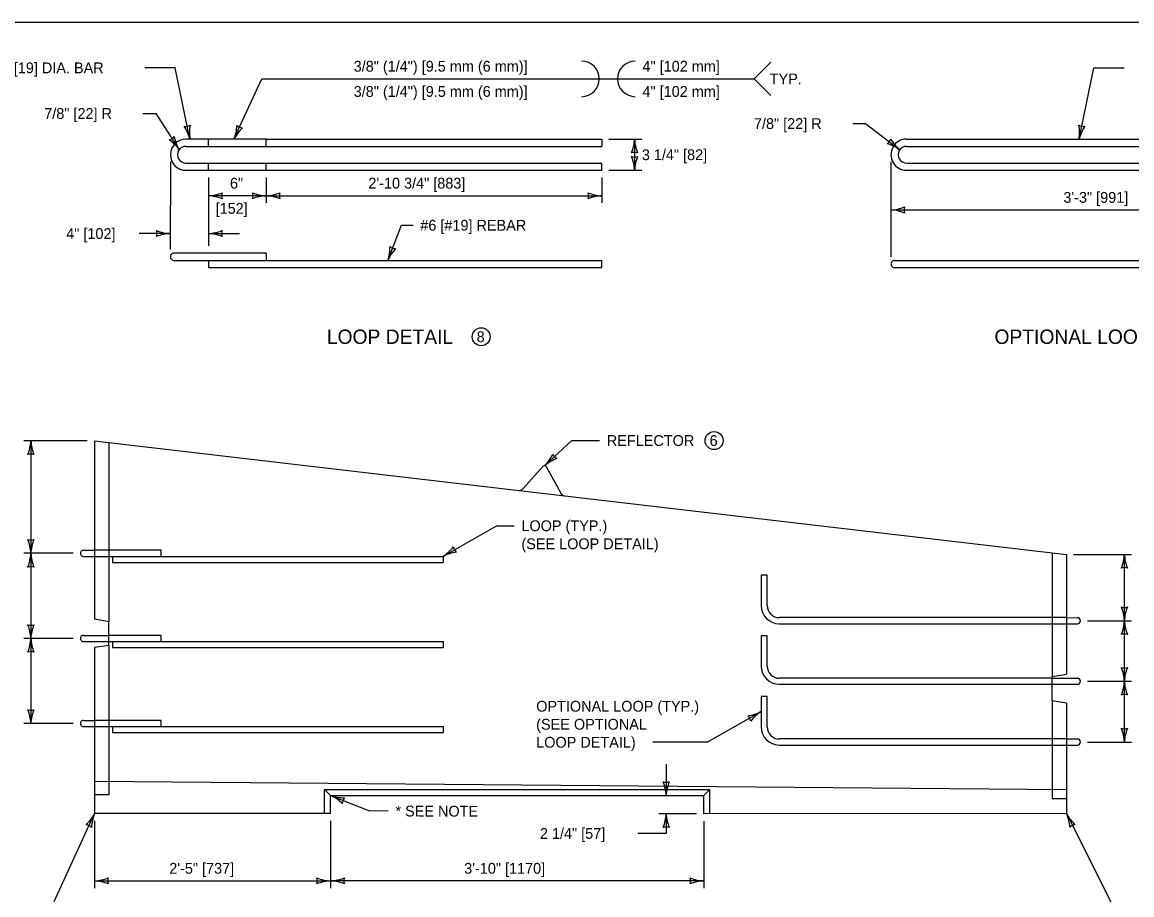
# Model space of a CAD drawing. Extents: x 49991.4 to 50021, y 49987.6 to 50011.4.
# Drawn here: x 50003.46 to 50009.63, y 49994.15 to 49999 of the extents above; entities that cross this region are included whole.
import ezdxf

# ---------------------------------------------------------------- set-up
doc = ezdxf.new("R2010")
doc.units = 0
for name, color, linetype in [('Level 1', 7, 'Continuous'), ('Level 2', 7, 'Continuous'), ('Level 3', 7, 'Continuous'), ('Level 4', 7, 'Continuous')]:
    doc.layers.add(name, color=color, linetype=linetype)

msp = doc.modelspace()

# ---------------------------------------------------------------- linework, layer by layer
at = {"layer": 'Level 1'}
for p, q in [((50004.8177, 49998.3499), (50004.3721, 49998.3499)), ((50004.8177, 49998.3499), (50006.6825, 49998.3499)), ((50004.8177, 49998.3098), (50004.8177, 49998.3499)), ((50006.6825, 49998.3499), (50006.6825, 49998.3098)), ((50008.376, 49998.3499), (50010.6665, 49998.3499)), ((50004.3718, 49998.3098), (50006.6825, 49998.3098)), ((50008.376, 49998.3098), (50010.6665, 49998.3098)), ((50004.3718, 49998.2169), (50006.6825, 49998.2169)), ((50004.8177, 49998.1767), (50004.8177, 49998.2169)), ((50006.6825, 49998.1767), (50006.6825, 49998.2169)), ((50008.3757, 49998.2169), (50010.6665, 49998.2169)), ((50004.3721, 49998.1767), (50004.8177, 49998.1767)), ((50004.8177, 49998.1767), (50006.6825, 49998.1767)), ((50006.6825, 49998.1767), (50006.6825, 49998.1767)), ((50008.376, 49998.1767), (50008.8216, 49998.1767)), ((50008.5005, 49998.1767), (50010.6665, 49998.1767)), ((50004.8177, 49997.7169), (50004.3055, 49997.7169)), ((50004.3055, 49997.6768), (50006.6825, 49997.6768)), ((50004.4966, 49997.6768), (50004.4966, 49997.6367)), ((50004.8177, 49997.7169), (50004.8177, 49997.6768)), ((50006.6825, 49997.6367), (50006.6825, 49997.6768)), ((50008.3092, 49997.6768), (50010.5663, 49997.6768)), ((50004.4966, 49997.6367), (50006.6825, 49997.6367)), ((50008.3092, 49997.6367), (50010.5663, 49997.6367)), ((50003.8641, 49996.6742), (50009.2642, 49996.0442)), ((50003.8641, 49996.6742), (50003.8641, 49995.6844)), ((50003.8022, 49996.0668), (50003.8641, 49996.0666)), ((50003.8022, 49996.033), (50003.8641, 49996.0329)), ((50009.2642, 49996.0442), (50009.2642, 49995.3789)), ((50009.2642, 49995.6926), (50009.3248, 49995.6925)), ((50003.9431, 49995.6691), (50003.8641, 49995.6844)), ((50003.9431, 49995.5388), (50003.9431, 49995.6691)), ((50009.2642, 49995.6589), (50009.3248, 49995.659)), ((50003.8023, 49995.5942), (50003.9431, 49995.5943)), ((50003.8023, 49995.5605), (50003.9431, 49995.5606)), ((50003.9431, 49995.5388), (50003.8642, 49995.5269)), ((50003.8642, 49995.5269), (50003.8642, 49994.6042)), ((50009.1855, 49995.3665), (50009.2642, 49995.3789)), ((50009.1855, 49995.2326), (50009.1855, 49995.3665)), ((50009.1855, 49995.3561), (50009.3248, 49995.3559)), ((50009.1855, 49995.3224), (50009.3248, 49995.3224)), ((50009.1855, 49995.2326), (50009.2642, 49995.2202)), ((50009.2642, 49995.2202), (50009.2642, 49994.6042)), ((50003.8023, 49995.1217), (50003.8642, 49995.122)), ((50003.8023, 49995.088), (50003.8642, 49995.0884)), ((50009.2642, 49995.0189), (50009.3248, 49995.0189)), ((50009.2642, 49994.9852), (50009.3248, 49994.9852)), ((50005.1425, 49994.6042), (50005.1425, 49994.7388)), ((50005.1425, 49994.7388), (50005.1761, 49994.705)), ((50005.1425, 49994.7388), (50007.2826, 49994.7388)), ((50005.1761, 49994.705), (50007.249, 49994.705)), ((50005.1761, 49994.6042), (50005.1761, 49994.705)), ((50007.2826, 49994.7388), (50007.249, 49994.705)), ((50007.249, 49994.6033), (50007.249, 49994.705)), ((50007.2826, 49994.6033), (50007.2826, 49994.7388)), ((50005.1761, 49994.6042), (50003.8642, 49994.6042)), ((50009.2642, 49994.6042), (50007.249, 49994.6033))]:
    msp.add_line(p, q, dxfattribs=at)
msp.add_lwpolyline([(49999.3835, 49998.9992), (50016.7501, 49998.9992), (50016.7501, 49987.7988), (49999.3835, 49987.7988)], close=True, dxfattribs=at)
for centre, radius, start, end in [((50004.3721, 49998.2633), 0.0866, 90, 270), ((50008.3758, 49998.2633), 0.0866, 89.85968, 270.14031), ((50004.3718, 49998.2633), 0.0465, 89.99697, 270.00303), ((50008.3755, 49998.2634), 0.0465, 89.36692, 270.33621), ((50004.3055, 49997.6969), 0.0201, 90.02933, 269.97067), ((50008.3092, 49997.6568), 0.02, 89.86684, 270.13311), ((50003.8022, 49996.0499), 0.0169, 89.95241, 270.04759), ((50009.3247, 49995.6758), 0.0168, 270.36731, 89.67733), ((50009.3248, 49995.3392), 0.0168, 270.24332, 90.00199), ((50003.8023, 49995.1049), 0.0169, 89.95713, 270.04287), ((50009.3248, 49995.002), 0.0169, 270.1612, 89.88321)]:
    msp.add_arc(centre, radius, start, end, dxfattribs=at)
msp.add_ellipse((50003.8023, 49995.5773), major_axis=(0, 0.0169), ratio=0.999599, start_param=0, end_param=3.141593, dxfattribs=at)
at = {"layer": 'Level 2'}
for centre in [(50006.0124, 49997.2526), (50007.3063, 49996.6761)]:
    msp.add_circle(centre, 0.05, dxfattribs=at)
at = {"layer": 'Level 3'}
for p, q in [((50007.5293, 49998.6845), (50007.6227, 49998.7779)), ((50007.5293, 49998.6845), (50007.6227, 49998.5913)), ((50004.1332, 49998.4923), (50004.2045, 49998.4923)), ((50004.2044, 49998.4922), (50004.3346, 49998.2911)), ((50008.0765, 49998.4362), (50008.1478, 49998.4362)), ((50008.1478, 49998.4362), (50008.3383, 49998.2912)), ((50006.7225, 49998.3499), (50006.905, 49998.3499)), ((50006.865, 49998.3499), (50006.865, 49998.1767)), ((50004.2855, 49998.2233), (50004.2853, 49997.7369)), ((50008.2892, 49998.2233), (50008.2892, 49997.6968)), ((50006.7225, 49998.1767), (50006.905, 49998.1767)), ((50004.4966, 49998.1367), (50004.4966, 49997.7569)), ((50004.8176, 49998.1367), (50004.8176, 49997.9953)), ((50006.6824, 49998.1367), (50006.6824, 49997.9953)), ((50004.8176, 49998.0353), (50004.4966, 49998.0353)), ((50004.8176, 49998.0353), (50006.6824, 49998.0353)), ((50010.6865, 49997.9563), (50008.2892, 49997.9563)), ((50004.2853, 49997.8254), (50004.1118, 49997.8254)), ((50004.4966, 49997.8254), (50004.6701, 49997.8254)), ((50003.8241, 49996.6742), (50003.4705, 49996.6742)), ((50003.5105, 49996.6742), (50003.5105, 49996.0498)), ((50006.3662, 49996.5368), (50006.5162, 49996.6761)), ((50006.5162, 49996.6761), (50006.6707, 49996.6761)), ((50006.3576, 49996.5335), (50006.2451, 49996.4091)), ((50006.3738, 49996.5316), (50006.4541, 49996.3843)), ((50006.0997, 49996.2029), (50005.8005, 49996.0329)), ((50006.0997, 49996.2029), (50006.1961, 49996.2029)), ((50003.7453, 49996.0498), (50003.4705, 49996.0498)), ((50003.5105, 49996.0498), (50003.5105, 49995.5773)), ((50009.3042, 49996.0442), (50009.6262, 49996.0442)), ((50009.5862, 49995.6758), (50009.5862, 49996.0442)), ((50009.3815, 49995.6758), (50009.6262, 49995.6758)), ((50009.5862, 49995.3392), (50009.5862, 49995.6758)), ((50003.7454, 49995.5773), (50003.4705, 49995.5773)), ((50003.5105, 49995.5773), (50003.5105, 49995.1048)), ((50009.3816, 49995.3392), (50009.6262, 49995.3392)), ((50009.5862, 49995.002), (50009.5862, 49995.3392)), ((50007.2686, 49995.0006), (50007.5678, 49995.1706)), ((50003.7454, 49995.1048), (50003.4705, 49995.1048)), ((50007.2686, 49995.0006), (50006.9657, 49995.0006)), ((50009.3817, 49995.002), (50009.6262, 49995.002)), ((50007.0404, 49994.8784), (50007.0404, 49994.705)), ((50005.1761, 49994.705), (50005.3919, 49994.6191)), ((50003.6395, 49994.1166), (50003.8642, 49994.6042)), ((50005.4962, 49994.6188), (50005.3919, 49994.6191)), ((50007.209, 49994.6033), (50007.0004, 49994.6033)), ((50007.0404, 49994.6033), (50007.0404, 49994.4942)), ((50009.2642, 49994.6042), (50009.548, 49994.0405)), ((50003.8642, 49994.5642), (50003.8642, 49994.1907)), ((50005.1761, 49994.5642), (50005.1761, 49994.1907)), ((50007.249, 49994.5633), (50007.249, 49994.1907)), ((50007.0404, 49994.4942), (50006.8832, 49994.4942)), ((50003.8642, 49994.2307), (50005.1761, 49994.2307)), ((50007.249, 49994.2307), (50005.1761, 49994.2307))]:
    msp.add_line(p, q, dxfattribs=at)
for points in [[(50004.3941, 49998.3499), (50004.3121, 49998.7457), (50004.1429, 49998.7457)], [(50009.3344, 49998.3499), (50009.4164, 49998.7457), (50009.5856, 49998.7457)], [(50004.639, 49998.3499), (50004.7931, 49998.6848), (50007.5293, 49998.6845)], [(50005.4941, 49997.6768), (50005.5693, 49997.8715), (50005.6343, 49997.8715)]]:
    msp.add_lwpolyline(points, dxfattribs=at)
for centre, radius, start, end in [((50006.5699, 49998.6845), 0.0989, 270, 90), ((50006.8687, 49998.6845), 0.0989, 90, 270), ((50004.3681, 49998.4754), 0.0548, 263.84977, 299.57213), ((50004.1686, 49998.2914), 0.233, 14.53826, 33.78811), ((50004.6135, 49998.386), 0.2223, 169.16696, 189.35047), ((50004.4228, 49998.4367), 0.233, 338.11863, 357.36848), ((50004.837, 49998.2487), 0.2223, 132.74733, 152.93084), ((50004.6926, 49998.4664), 0.0548, 227.43014, 263.1525), ((50009.115, 49998.386), 0.2223, 350.64953, 10.83304), ((50009.3604, 49998.4755), 0.0548, 240.42787, 276.15023), ((50009.5599, 49998.2914), 0.233, 146.21189, 165.46174), ((50004.2649, 49998.3988), 0.0548, 285.05282, 320.77518), ((50004.1454, 49998.155), 0.233, 35.74131, 54.99116), ((50004.526, 49998.4041), 0.2223, 190.37001, 210.55352), ((50006.6429, 49998.3591), 0.2223, 337.45601, 357.63952), ((50007.0978, 49998.3614), 0.233, 182.82731, 202.07716), ((50008.2362, 49998.3689), 0.0548, 304.85047, 340.57283), ((50008.4801, 49998.4624), 0.2223, 210.16766, 230.35117), ((50006.865, 49998.2217), 0.0548, 72.13882, 107.86118), ((50008.2064, 49998.0991), 0.233, 55.53896, 74.78881), ((50006.865, 49998.3049), 0.0548, 252.13882, 287.86118), ((50006.6323, 49998.1652), 0.233, 2.82731, 22.07716), ((50007.0872, 49998.1675), 0.2223, 157.45601, 177.63952), ((50004.4851, 49998.268), 0.233, 272.82731, 292.07716), ((50004.4875, 49997.8132), 0.2223, 67.45601, 87.63952), ((50004.6248, 49998.0353), 0.0548, 162.13882, 197.86118), ((50004.8267, 49998.2574), 0.2223, 247.45601, 267.63952), ((50004.6893, 49998.0353), 0.0548, 342.13882, 17.86118), ((50004.8291, 49997.8026), 0.233, 92.82731, 112.07716), ((50004.8061, 49998.268), 0.233, 272.82731, 292.07716), ((50004.8084, 49997.8132), 0.2223, 67.45601, 87.63952), ((50004.9458, 49998.0353), 0.0548, 162.13882, 197.86118), ((50006.6916, 49998.2574), 0.2223, 247.45601, 267.63952), ((50006.5542, 49998.0353), 0.0548, 342.13882, 17.86118), ((50006.6939, 49997.8026), 0.233, 92.82731, 112.07716), ((50008.2777, 49998.189), 0.233, 272.82731, 292.07716), ((50008.4174, 49997.9563), 0.0548, 162.13882, 197.86118), ((50008.28, 49997.7341), 0.2223, 67.45601, 87.63952), ((50004.2945, 49998.0475), 0.2223, 247.45601, 267.63952), ((50004.1571, 49997.8254), 0.0548, 342.13882, 17.86118), ((50004.2968, 49997.5927), 0.233, 92.82731, 112.07716), ((50004.4851, 49998.0581), 0.233, 272.82731, 292.07716), ((50004.4875, 49997.6033), 0.2223, 67.45601, 87.63952), ((50004.6249, 49997.8254), 0.0548, 162.13882, 197.86118), ((50005.2729, 49997.7498), 0.233, 341.72472, 0.97457), ((50005.6981, 49997.5883), 0.2223, 136.35342, 156.53693), ((50005.5403, 49997.7964), 0.0548, 231.03623, 266.75859), ((50003.2883, 49996.6833), 0.2223, 337.45803, 357.64153), ((50003.7432, 49996.6857), 0.233, 182.82933, 202.07918), ((50003.5105, 49996.546), 0.0548, 72.14083, 107.86319), ((50006.1994, 49996.6995), 0.233, 315.70582, 334.95567), ((50006.5106, 49996.3678), 0.2223, 110.33452, 130.51802), ((50006.4601, 49996.624), 0.0548, 205.01732, 240.73968), ((50006.365, 49996.5268), 0.01, 28.58922, 137.89134), ((50006.2229, 49996.4292), 0.03, 263.24028, 317.89134), ((50006.4804, 49996.3987), 0.03, 208.58922, 253.11239), ((50003.5105, 49996.178), 0.0548, 252.14083, 287.86319), ((50003.2778, 49996.0383), 0.233, 2.82932, 22.07917), ((50003.7326, 49996.0407), 0.2223, 157.45802, 177.64153), ((50005.6828, 49996.2215), 0.2223, 301.96607, 322.14958), ((50005.912, 49996.0962), 0.0548, 191.74441, 227.46677), ((50003.2883, 49996.059), 0.2223, 337.45803, 357.64153), ((50003.7432, 49996.0613), 0.233, 182.82933, 202.07918), ((50005.9055, 49995.8248), 0.233, 97.52843, 116.77828), ((50009.3641, 49996.0533), 0.2223, 337.45601, 357.63952), ((50009.8189, 49996.0557), 0.233, 182.82731, 202.07716), ((50003.5105, 49995.9216), 0.0548, 72.14083, 107.86319), ((50009.5862, 49995.916), 0.0548, 72.13882, 107.86118), ((50009.5862, 49995.804), 0.0548, 252.13882, 287.86118), ((50009.3535, 49995.6643), 0.233, 2.82731, 22.07716), ((50009.8084, 49995.6666), 0.2223, 157.45601, 177.63952), ((50003.5105, 49995.7055), 0.0548, 252.14083, 287.86319), ((50003.2778, 49995.5658), 0.233, 2.82932, 22.07917), ((50003.7326, 49995.5682), 0.2223, 157.45802, 177.64153), ((50009.3641, 49995.6849), 0.2223, 337.45601, 357.63952), ((50009.8189, 49995.6873), 0.233, 182.82731, 202.07716), ((50003.2884, 49995.5865), 0.2223, 337.45803, 357.64153), ((50003.7432, 49995.5888), 0.233, 182.82933, 202.07918), ((50009.5862, 49995.5476), 0.0548, 72.13882, 107.86118), ((50003.5105, 49995.4491), 0.0548, 72.14083, 107.86319), ((50009.5862, 49995.4674), 0.0548, 252.13882, 287.86118), ((50009.3535, 49995.3277), 0.233, 2.82731, 22.07716), ((50009.8084, 49995.33), 0.2223, 157.45601, 177.63952), ((50009.3641, 49995.3483), 0.2223, 337.45601, 357.63952), ((50009.8189, 49995.3507), 0.233, 182.82731, 202.07716), ((50009.5862, 49995.211), 0.0548, 72.13882, 107.86118), ((50003.5105, 49995.233), 0.0548, 252.14083, 287.86319), ((50003.2778, 49995.0933), 0.233, 2.82932, 22.07917), ((50003.7326, 49995.0957), 0.2223, 157.45802, 177.64153), ((50007.4628, 49995.3786), 0.233, 277.52842, 296.77828), ((50007.4563, 49995.1073), 0.0548, 11.74441, 47.46677), ((50007.6855, 49994.982), 0.2223, 121.96607, 142.14957), ((50009.5862, 49995.1302), 0.0548, 252.13882, 287.86118), ((50009.3535, 49994.9905), 0.233, 2.82731, 22.07716), ((50009.8084, 49994.9928), 0.2223, 157.45601, 177.63952), ((50007.0404, 49994.8332), 0.0548, 252.13882, 287.86118), ((50006.8077, 49994.6935), 0.233, 2.82731, 22.07716), ((50007.2625, 49994.6958), 0.2223, 157.45601, 177.63952), ((50005.2497, 49994.9148), 0.2223, 250.65985, 270.84336), ((50005.0794, 49994.493), 0.233, 46.22221, 65.47206), ((50005.2952, 49994.6576), 0.0548, 140.43819, 176.16055), ((50003.6663, 49994.7055), 0.2223, 312.71539, 332.89889), ((50004.0803, 49994.5172), 0.233, 158.08669, 177.33654), ((50006.8183, 49994.6124), 0.2223, 337.45601, 357.63952), ((50007.2731, 49994.6148), 0.233, 182.82731, 202.07716), ((50009.0617, 49994.5125), 0.2223, 4.18325, 24.36676), ((50009.4669, 49994.7191), 0.233, 209.55455, 228.8044), ((50003.8105, 49994.4877), 0.0548, 47.39819, 83.12056), ((50007.0404, 49994.4751), 0.0548, 72.13882, 107.86118), ((50009.3219, 49994.4897), 0.0548, 98.86606, 134.58842), ((50003.8527, 49994.4634), 0.233, 272.82731, 292.07716), ((50003.855, 49994.0086), 0.2223, 67.45601, 87.63952), ((50003.9924, 49994.2307), 0.0548, 162.13882, 197.86118), ((50005.1853, 49994.4528), 0.2223, 247.45601, 267.63952), ((50005.0479, 49994.2307), 0.0548, 342.13882, 17.86118), ((50005.1876, 49993.998), 0.233, 92.82731, 112.07716), ((50005.1646, 49994.4634), 0.233, 272.82731, 292.07716), ((50005.1669, 49994.0086), 0.2223, 67.45601, 87.63952), ((50005.3043, 49994.2307), 0.0548, 162.13882, 197.86118), ((50007.2582, 49994.4528), 0.2223, 247.45601, 267.63952), ((50007.1208, 49994.2307), 0.0548, 342.13882, 17.86118), ((50007.2605, 49993.998), 0.233, 92.82731, 112.07716)]:
    msp.add_arc(centre, radius, start, end, dxfattribs=at)
at = {"layer": 'Level 4'}
for p, q in [((50004.4966, 49998.3098), (50004.4966, 49998.3499)), ((50004.4966, 49998.1767), (50004.4966, 49998.2169)), ((50003.9431, 49996.665), (50003.9431, 49995.6691)), ((50004.2338, 49996.0666), (50003.8641, 49996.0666)), ((50004.2338, 49996.0329), (50004.2338, 49996.0666)), ((50003.8641, 49996.0329), (50005.8005, 49996.0329)), ((50003.9642, 49996.0329), (50003.9642, 49995.9992)), ((50003.9642, 49995.9992), (50005.8005, 49995.9992)), ((50005.8005, 49996.0329), (50005.8005, 49995.9992)), ((50009.1855, 49996.0534), (50009.1855, 49995.3665)), ((50007.6015, 49995.9289), (50007.5678, 49995.9289)), ((50007.5678, 49995.9289), (50007.5678, 49995.7599)), ((50007.6015, 49995.7599), (50007.6015, 49995.9289)), ((50009.2642, 49995.6926), (50007.6687, 49995.6926)), ((50007.6687, 49995.6589), (50009.2642, 49995.6589)), ((50004.234, 49995.5943), (50003.9431, 49995.5943)), ((50004.234, 49995.5606), (50004.234, 49995.5943)), ((50007.6017, 49995.5924), (50007.568, 49995.5924)), ((50007.568, 49995.5924), (50007.568, 49995.4233)), ((50007.6017, 49995.4233), (50007.6017, 49995.5924)), ((50003.9431, 49995.5606), (50005.801, 49995.5606)), ((50003.9431, 49995.5388), (50003.9431, 49994.7095)), ((50003.9642, 49995.5606), (50003.9642, 49995.5269)), ((50003.9642, 49995.5269), (50005.8005, 49995.5269)), ((50005.8005, 49995.5606), (50005.8005, 49995.5269)), ((50005.8005, 49995.5269), (50005.8005, 49995.5269)), ((50009.1855, 49995.3561), (50007.669, 49995.3561)), ((50007.669, 49995.3224), (50009.1855, 49995.3224)), ((50007.6015, 49995.2551), (50007.5678, 49995.2551)), ((50007.5678, 49995.2551), (50007.5678, 49995.0861)), ((50007.6015, 49995.0861), (50007.6015, 49995.2551)), ((50009.1855, 49995.2326), (50009.1855, 49994.6885)), ((50004.2338, 49995.122), (50003.8642, 49995.122)), ((50003.8642, 49995.0884), (50005.8005, 49995.0884)), ((50003.9642, 49995.0884), (50003.9642, 49995.0546)), ((50004.2338, 49995.0884), (50004.2338, 49995.122)), ((50005.8005, 49995.0884), (50005.8005, 49995.0546)), ((50003.9642, 49995.0546), (50005.8005, 49995.0546)), ((50009.2642, 49995.0189), (50007.6687, 49995.0189)), ((50007.6687, 49994.9852), (50009.2642, 49994.9852)), ((50003.8642, 49994.7838), (50009.2642, 49994.7388)), ((50003.9431, 49994.7095), (50003.8642, 49994.7095)), ((50003.9431, 49994.7095), (50003.9431, 49994.7095)), ((50009.1855, 49994.6885), (50009.2642, 49994.6885))]:
    msp.add_line(p, q, dxfattribs=at)
for centre, radius, start, end in [((50007.6695, 49995.7606), 0.1017, 180.43427, 269.60389), ((50007.6687, 49995.7599), 0.0672, 180, 270), ((50007.6697, 49995.4241), 0.1017, 180.43427, 269.60389), ((50007.669, 49995.4233), 0.0672, 180, 270), ((50007.6695, 49995.0869), 0.1017, 180.43427, 269.60389), ((50007.6687, 49995.0861), 0.0672, 180, 270)]:
    msp.add_arc(centre, radius, start, end, dxfattribs=at)

# ---------------------------------------------------------------- texts
at = {"layer": 'Level 2'}
for s, height, p in [('3/4" [19] DIA. BAR', 0.06, (50003.2532, 49998.7157)), ('3/8" (1/4") [9.5 mm (6 mm)]', 0.06, (50005.304, 49998.7246)), ('4" [102 mm]', 0.06, (50006.9086, 49998.7246)), ('TYP.', 0.06, (50007.6156, 49998.6543)), ('3/8" (1/4") [9.5 mm (6 mm)]', 0.06, (50005.3041, 49998.5847)), ('4" [102 mm]', 0.06, (50006.9086, 49998.5846)), ('7/8" [22] R', 0.06, (50003.5846, 49998.4623)), ('7/8" [22] R', 0.06, (50007.5279, 49998.4062)), ('3 1/4" [82]', 0.06, (50006.905, 49998.2333)), ('6"', 0.06, (50004.6167, 49998.0753)), ('2\'-10 3/4" [883]', 0.06, (50005.3857, 49998.0753)), ('3\'-3" [991]', 0.06, (50009.2472, 49997.9963)), ('[152]', 0.06, (50004.5369, 49997.9353)), ('4" [102]', 0.06, (50003.7069, 49997.7954)), ('#6 [#19] REBAR', 0.06, (50005.6743, 49997.8415)), ('LOOP DETAIL', 0.08, (50005.155, 49997.2126)), ('OPTIONAL LOOP DETAIL', 0.08, (50008.8643, 49997.2126)), ('8', 0.06, (50005.9874, 49997.2226)), ('REFLECTOR', 0.06, (50006.7107, 49996.6461)), ('6', 0.06, (50007.2818, 49996.6461)), ('LOOP (TYP.)', 0.06, (50006.2361, 49996.1729)), ('(SEE LOOP DETAIL)', 0.06, (50006.2361, 49996.0729)), ('OPTIONAL LOOP (TYP.)', 0.06, (50006.3181, 49995.1706)), ('(SEE OPTIONAL', 0.06, (50006.3181, 49995.0706)), ('LOOP DETAIL)', 0.06, (50006.3181, 49994.9706)), ('2 1/4" [57]', 0.06, (50006.3387, 49994.4642)), ('2\'-5" [737]', 0.06, (50004.2795, 49994.2707)), ('3\'-10" [1170]', 0.06, (50005.9181, 49994.2707))]:
    msp.add_text(s, height=height, dxfattribs=at).set_placement(p)
msp.add_text('* SEE NOTE ', height=0.06, rotation=359.82998, dxfattribs=at).set_placement((50005.5361, 49994.5888))

doc.saveas('drawing.dxf')
